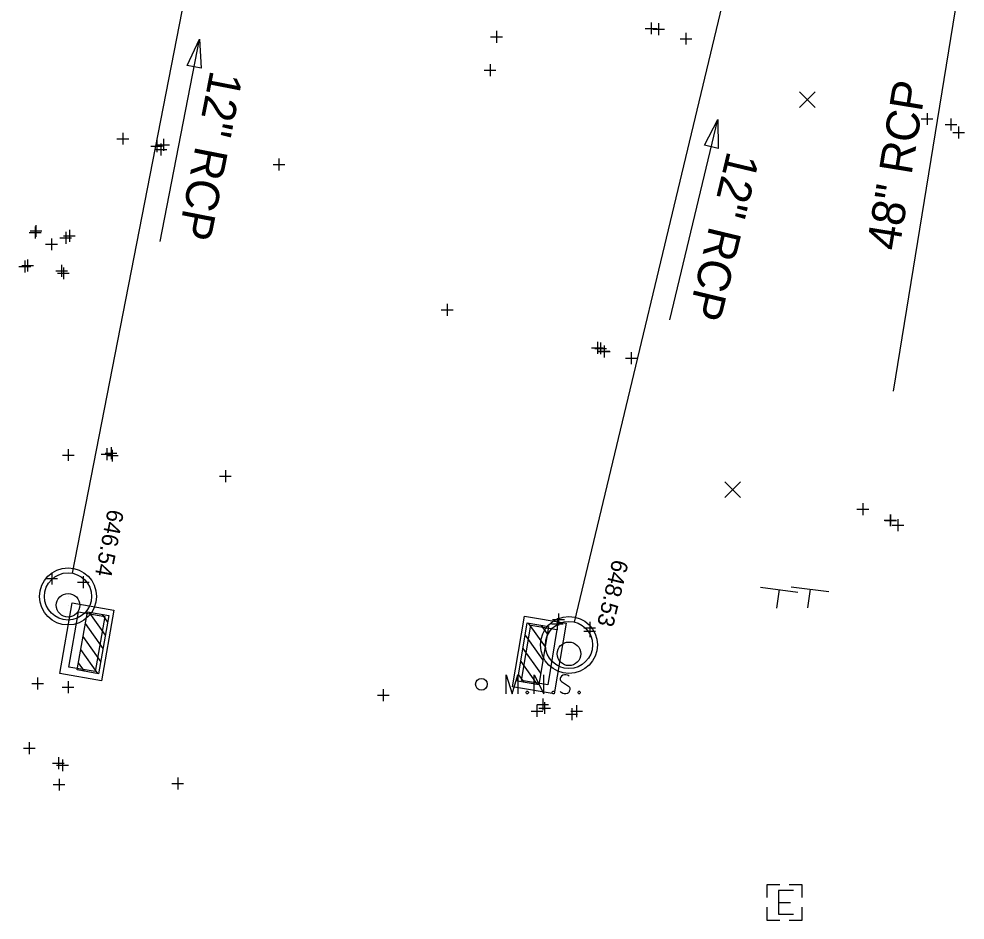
# Model space of a CAD drawing. Extents: x 2188719 to 2189819, y 654569 to 659504.
# Drawn here: x 2189542.6 to 2189622.9, y 656253.5 to 656329.9 of the extents above; entities that cross this region are included whole.
import ezdxf

# ---------------------------------------------------------------- set-up
doc = ezdxf.new("R2010")
doc.units = 0
for name, color, linetype in [('DR_X_Cells', 7, 'Continuous'), ('DR_X_Storm_Sewer', 7, 'Continuous'), ('DR_X_Text', 7, 'Continuous'), ('GK_Drainage_Nodes', 7, 'Continuous'), ('SC_Scratch1', 7, 'Continuous'), ('SN_X_Public', 7, 'Continuous'), ('SV_P_Control_Cells_Set', 7, 'Continuous'), ('SV_X_Random_Point', 7, 'Continuous'), ('SV_X_Shot_Marker', 7, 'Continuous'), ('UT_X_Electric_Cells', 7, 'Continuous')]:
    doc.layers.add(name, color=color, linetype=linetype)

msp = doc.modelspace()

# ---------------------------------------------------------------- linework, layer by layer
at = {"layer": 'DR_X_Cells'}
for p, q in [((2189549.977, 656277.639), (2189548.605, 656279.591)), ((2189550.173, 656278.752), (2189549.721, 656279.395)), ((2189549.781, 656276.526), (2189548.292, 656278.645)), ((2189585.812, 656278.663), (2189587.255, 656276.642)), ((2189586.929, 656278.475), (2189587.442, 656277.756)), ((2189585.563, 656277.635), (2189587.067, 656275.527)), ((2189549.585, 656275.414), (2189548.097, 656277.532)), ((2189549.329, 656274.387), (2189547.901, 656276.419)), ((2189585.375, 656276.521), (2189586.88, 656274.413)), ((2189548.213, 656274.583), (2189547.705, 656275.307)), ((2189585.188, 656275.406), (2189586.574, 656273.465)), ((2189585, 656274.292), (2189585.457, 656273.653))]:
    msp.add_line(p, q, dxfattribs=at)
for points in [[(2189546.107, 656274.404), (2189547.161, 656280.395), (2189550.691, 656279.774), (2189549.637, 656273.783)], [(2189546.88, 656274.945), (2189547.703, 656279.623), (2189549.919, 656279.233), (2189549.096, 656274.555)], [(2189547.597, 656274.692), (2189548.463, 656279.616), (2189550.269, 656279.298), (2189549.402, 656274.374)], [(2189589.034, 656278.67), (2189588.024, 656272.671), (2189584.49, 656273.266), (2189585.499, 656279.265)], [(2189587.546, 656278.371), (2189586.716, 656273.441), (2189584.908, 656273.745), (2189585.738, 656278.676)], [(2189588.265, 656278.124), (2189587.476, 656273.439), (2189585.258, 656273.813), (2189586.046, 656278.497)]]:
    msp.add_lwpolyline(points, close=True, dxfattribs=at)
for centre, radius in [((2189546.811, 656280.929), 2.417), ((2189546.811, 656280.929), 2), ((2189546.811, 656280.179), 1), ((2189589.279, 656276.813), 2.417), ((2189589.279, 656276.813), 2), ((2189589.279, 656276.063), 1)]:
    msp.add_circle(centre, radius, dxfattribs=at)
at = {"layer": 'DR_X_Storm_Sewer'}
for p, q in [((2189547.183, 656282.894), (2189561.205, 656354.68)), ((2189589.745, 656278.758), (2189605.751, 656345.53)), ((2189622.866, 656335.815), (2189616.759, 656298.323))]:
    msp.add_line(p, q, dxfattribs=at)
at = {"layer": 'DR_X_Text'}
for p, q in [((2189554.612, 656311.019), (2189557.965, 656328.181)), ((2189597.837, 656304.366), (2189601.913, 656321.37))]:
    msp.add_line(p, q, dxfattribs=at)
for points in [[(2189557.965, 656328.181), (2189558.093, 656325.711), (2189556.916, 656325.941)], [(2189601.913, 656321.37), (2189601.937, 656318.897), (2189600.771, 656319.176)]]:
    msp.add_lwpolyline(points, close=True, dxfattribs=at)
at = {"layer": 'GK_Drainage_Nodes'}
for p, q in [((2189546.811, 656282.929), (2189546.811, 656282.929)), ((2189546.811, 656280.929), (2189546.811, 656280.929)), ((2189546.811, 656280.929), (2189546.811, 656280.929)), ((2189546.811, 656280.179), (2189546.811, 656280.179)), ((2189548.811, 656279.428), (2189548.811, 656279.428)), ((2189546.811, 656278.929), (2189546.811, 656278.929)), ((2189589.279, 656278.813), (2189589.279, 656278.813)), ((2189587.155, 656278.31), (2189587.155, 656278.31)), ((2189546.635, 656277.4), (2189546.635, 656277.4)), ((2189547.291, 656277.284), (2189547.291, 656277.284)), ((2189548.03, 656277.154), (2189548.03, 656277.154)), ((2189548.03, 656277.154), (2189548.03, 656277.154)), ((2189548.399, 656277.089), (2189548.399, 656277.089)), ((2189549.507, 656276.894), (2189549.507, 656276.894)), ((2189550.164, 656276.778), (2189550.164, 656276.778)), ((2189589.279, 656276.813), (2189589.279, 656276.813)), ((2189589.279, 656276.813), (2189589.279, 656276.813)), ((2189584.994, 656276.266), (2189584.994, 656276.266)), ((2189585.652, 656276.155), (2189585.652, 656276.155)), ((2189586.761, 656275.968), (2189586.761, 656275.968)), ((2189589.279, 656276.063), (2189589.279, 656276.063)), ((2189587.131, 656275.906), (2189587.131, 656275.906)), ((2189587.131, 656275.906), (2189587.131, 656275.906)), ((2189587.871, 656275.782), (2189587.871, 656275.782)), ((2189588.528, 656275.671), (2189588.528, 656275.671)), ((2189547.988, 656274.75), (2189547.988, 656274.75)), ((2189589.279, 656274.813), (2189589.279, 656274.813)), ((2189586.367, 656273.626), (2189586.367, 656273.626))]:
    msp.add_line(p, q, dxfattribs=at)
for centre in [(2189546.811, 656280.929), (2189589.279, 656276.813)]:
    msp.add_circle(centre, 2, dxfattribs=at)
at = {"layer": 'SN_X_Public'}
for p, q in [((2189605.518, 656281.725), (2189608.688, 656281.293)), ((2189608.133, 656281.753), (2189611.307, 656281.345)), ((2189607.103, 656281.509), (2189606.887, 656279.924)), ((2189609.72, 656281.549), (2189609.516, 656279.962))]:
    msp.add_line(p, q, dxfattribs=at)
at = {"layer": 'SV_P_Control_Cells_Set'}
for points in [[(2189583.952, 656272.681), (2189583.952, 656274.281), (2189584.459, 656272.681), (2189584.944, 656274.281), (2189584.944, 656272.681)], [(2189586.322, 656272.681), (2189586.322, 656274.281), (2189587.149, 656272.681), (2189587.149, 656274.281)], [(2189589.299, 656274.168), (2189589.277, 656274.193), (2189589.243, 656274.218), (2189589.144, 656274.256), (2189589.023, 656274.281), (2189588.935, 656274.281), (2189588.902, 656274.281), (2189588.758, 656274.244), (2189588.637, 656274.168), (2189588.56, 656274.067), (2189588.538, 656273.966), (2189588.538, 656273.891), (2189588.56, 656273.79), (2189588.648, 656273.702), (2189589.255, 656273.324), (2189589.31, 656273.274), (2189589.332, 656273.223), (2189589.354, 656273.148), (2189589.354, 656273.072), (2189589.343, 656272.996), (2189589.332, 656272.946), (2189589.31, 656272.883), (2189589.288, 656272.833), (2189589.265, 656272.795), (2189589.232, 656272.757), (2189589.199, 656272.732), (2189589.155, 656272.707), (2189589.122, 656272.694), (2189589.023, 656272.681), (2189588.869, 656272.681), (2189588.77, 656272.707), (2189588.626, 656272.795), (2189588.538, 656272.87)], [(2189585.716, 656272.896), (2189585.771, 656272.896), (2189585.804, 656272.87), (2189585.837, 656272.82), (2189585.837, 656272.757), (2189585.804, 656272.707), (2189585.771, 656272.681), (2189585.716, 656272.681), (2189585.683, 656272.707), (2189585.65, 656272.757), (2189585.65, 656272.82), (2189585.683, 656272.87), (2189585.716, 656272.896)], [(2189587.932, 656272.896), (2189587.987, 656272.896), (2189588.02, 656272.87), (2189588.053, 656272.82), (2189588.053, 656272.757), (2189588.02, 656272.707), (2189587.987, 656272.681), (2189587.932, 656272.681), (2189587.899, 656272.707), (2189587.866, 656272.757), (2189587.866, 656272.82), (2189587.899, 656272.87), (2189587.932, 656272.896)], [(2189590.114, 656272.896), (2189590.169, 656272.896), (2189590.203, 656272.87), (2189590.235, 656272.82), (2189590.235, 656272.757), (2189590.203, 656272.707), (2189590.169, 656272.681), (2189590.114, 656272.681), (2189590.081, 656272.707), (2189590.048, 656272.757), (2189590.048, 656272.82), (2189590.081, 656272.87), (2189590.114, 656272.896)]]:
    msp.add_lwpolyline(points, dxfattribs=at)
msp.add_circle((2189581.862, 656273.481), 0.497, dxfattribs=at)
at = {"layer": 'SV_X_Random_Point'}
for p, q in [((2189608.818, 656322.368), (2189610.152, 656323.703)), ((2189608.818, 656323.703), (2189610.152, 656322.368)), ((2189602.504, 656289.313), (2189603.838, 656290.649)), ((2189602.504, 656290.649), (2189603.838, 656289.313))]:
    msp.add_line(p, q, dxfattribs=at)
at = {"layer": 'SV_X_Shot_Marker'}
for p, q in [((2189595.754, 656329.088), (2189596.754, 656329.088)), ((2189596.254, 656329.588), (2189596.254, 656328.588)), ((2189596.254, 656329.088), (2189596.254, 656329.088)), ((2189596.378, 656329.02), (2189597.378, 656329.02)), ((2189596.878, 656329.52), (2189596.878, 656328.52)), ((2189596.878, 656329.02), (2189596.878, 656329.02)), ((2189582.641, 656328.378), (2189583.641, 656328.378)), ((2189583.141, 656328.878), (2189583.141, 656327.878)), ((2189583.141, 656328.378), (2189583.141, 656328.378)), ((2189598.704, 656328.217), (2189599.704, 656328.217)), ((2189599.204, 656328.717), (2189599.204, 656327.717)), ((2189599.204, 656328.217), (2189599.204, 656328.217)), ((2189582.589, 656326.049), (2189582.589, 656325.049)), ((2189582.089, 656325.549), (2189583.089, 656325.549)), ((2189582.589, 656325.549), (2189582.589, 656325.549)), ((2189619.644, 656321.913), (2189619.644, 656320.913)), ((2189619.144, 656321.413), (2189620.144, 656321.413)), ((2189619.644, 656321.413), (2189619.644, 656321.413)), ((2189621.165, 656320.937), (2189622.165, 656320.937)), ((2189621.665, 656321.437), (2189621.665, 656320.437)), ((2189621.665, 656320.937), (2189621.665, 656320.937)), ((2189551.45, 656320.237), (2189551.45, 656319.237)), ((2189621.817, 656320.26), (2189622.817, 656320.26)), ((2189622.317, 656320.76), (2189622.317, 656319.76)), ((2189622.317, 656320.26), (2189622.317, 656320.26)), ((2189550.95, 656319.737), (2189551.95, 656319.737)), ((2189551.45, 656319.737), (2189551.45, 656319.737)), ((2189554.329, 656319.602), (2189554.329, 656318.602)), ((2189554.686, 656319.321), (2189554.686, 656318.321)), ((2189554.915, 656319.713), (2189554.915, 656318.713)), ((2189553.829, 656319.102), (2189554.829, 656319.102)), ((2189554.186, 656318.821), (2189555.186, 656318.821)), ((2189554.329, 656319.102), (2189554.329, 656319.102)), ((2189554.415, 656319.213), (2189555.415, 656319.213)), ((2189554.686, 656318.821), (2189554.686, 656318.821)), ((2189554.915, 656319.213), (2189554.915, 656319.213)), ((2189564.694, 656318.049), (2189564.694, 656317.049)), ((2189564.194, 656317.549), (2189565.194, 656317.549)), ((2189564.694, 656317.549), (2189564.694, 656317.549)), ((2189544.018, 656312.28), (2189544.018, 656311.28)), ((2189544.087, 656312.419), (2189544.087, 656311.419)), ((2189543.518, 656311.78), (2189544.518, 656311.78)), ((2189543.587, 656311.919), (2189544.587, 656311.919)), ((2189544.018, 656311.78), (2189544.018, 656311.78)), ((2189544.087, 656311.919), (2189544.087, 656311.919)), ((2189545.41, 656311.281), (2189545.41, 656310.281)), ((2189546.109, 656311.334), (2189547.109, 656311.334)), ((2189546.427, 656311.499), (2189547.427, 656311.499)), ((2189546.609, 656311.834), (2189546.609, 656310.834)), ((2189546.609, 656311.334), (2189546.609, 656311.334)), ((2189546.927, 656311.999), (2189546.927, 656310.999)), ((2189546.927, 656311.499), (2189546.927, 656311.499)), ((2189544.91, 656310.781), (2189545.91, 656310.781)), ((2189545.41, 656310.781), (2189545.41, 656310.781)), ((2189542.645, 656308.9), (2189543.645, 656308.9)), ((2189542.884, 656308.985), (2189543.884, 656308.985)), ((2189543.145, 656309.4), (2189543.145, 656308.4)), ((2189543.145, 656308.9), (2189543.145, 656308.9)), ((2189543.384, 656309.485), (2189543.384, 656308.485)), ((2189543.384, 656308.985), (2189543.384, 656308.985)), ((2189546.261, 656309.038), (2189546.261, 656308.038)), ((2189545.761, 656308.538), (2189546.761, 656308.538)), ((2189545.919, 656308.327), (2189546.919, 656308.327)), ((2189546.261, 656308.538), (2189546.261, 656308.538)), ((2189546.419, 656308.827), (2189546.419, 656307.827)), ((2189546.419, 656308.327), (2189546.419, 656308.327)), ((2189578.951, 656305.723), (2189578.951, 656304.723)), ((2189578.451, 656305.223), (2189579.451, 656305.223)), ((2189578.951, 656305.223), (2189578.951, 656305.223)), ((2189591.695, 656302.509), (2189591.695, 656301.509)), ((2189591.965, 656302.459), (2189591.965, 656301.459)), ((2189591.195, 656302.009), (2189592.195, 656302.009)), ((2189591.465, 656301.959), (2189592.465, 656301.959)), ((2189591.695, 656302.009), (2189591.695, 656302.009)), ((2189591.754, 656301.717), (2189592.754, 656301.717)), ((2189591.77, 656301.695), (2189592.77, 656301.695)), ((2189591.965, 656301.959), (2189591.965, 656301.959)), ((2189592.254, 656302.217), (2189592.254, 656301.217)), ((2189592.254, 656301.717), (2189592.254, 656301.717)), ((2189592.27, 656302.195), (2189592.27, 656301.195)), ((2189592.27, 656301.695), (2189592.27, 656301.695)), ((2189594.068, 656301.129), (2189595.068, 656301.129)), ((2189594.568, 656301.629), (2189594.568, 656300.629)), ((2189594.568, 656301.129), (2189594.568, 656301.129)), ((2189546.33, 656292.915), (2189547.33, 656292.915)), ((2189546.83, 656293.415), (2189546.83, 656292.415)), ((2189546.83, 656292.915), (2189546.83, 656292.915)), ((2189549.608, 656292.993), (2189550.608, 656292.993)), ((2189549.954, 656293.076), (2189550.954, 656293.076)), ((2189550.058, 656292.864), (2189551.058, 656292.864)), ((2189550.108, 656293.493), (2189550.108, 656292.493)), ((2189550.108, 656292.993), (2189550.108, 656292.993)), ((2189550.454, 656293.576), (2189550.454, 656292.576)), ((2189550.454, 656293.076), (2189550.454, 656293.076)), ((2189550.558, 656293.364), (2189550.558, 656292.364)), ((2189550.558, 656292.864), (2189550.558, 656292.864)), ((2189560.147, 656291.622), (2189560.147, 656290.622)), ((2189559.647, 656291.122), (2189560.647, 656291.122)), ((2189560.147, 656291.122), (2189560.147, 656291.122)), ((2189614.199, 656288.832), (2189614.199, 656287.832)), ((2189613.699, 656288.332), (2189614.699, 656288.332)), ((2189614.199, 656288.332), (2189614.199, 656288.332)), ((2189616.014, 656287.386), (2189617.014, 656287.386)), ((2189616.055, 656287.38), (2189617.055, 656287.38)), ((2189616.514, 656287.886), (2189616.514, 656286.886)), ((2189616.514, 656287.386), (2189616.514, 656287.386)), ((2189616.555, 656287.88), (2189616.555, 656286.88)), ((2189616.555, 656287.38), (2189616.555, 656287.38)), ((2189617.171, 656287.471), (2189617.171, 656286.471)), ((2189616.671, 656286.971), (2189617.671, 656286.971)), ((2189617.171, 656286.971), (2189617.171, 656286.971)), ((2189544.923, 656282.45), (2189545.923, 656282.45)), ((2189545.423, 656282.95), (2189545.423, 656281.95)), ((2189545.423, 656282.45), (2189545.423, 656282.45)), ((2189548.1, 656282.634), (2189548.1, 656281.634)), ((2189547.6, 656282.134), (2189548.6, 656282.134)), ((2189548.1, 656282.134), (2189548.1, 656282.134)), ((2189588.39, 656279.47), (2189588.39, 656278.47)), ((2189587.791, 656278.593), (2189588.791, 656278.593)), ((2189587.89, 656278.97), (2189588.89, 656278.97)), ((2189588.291, 656279.093), (2189588.291, 656278.093)), ((2189588.291, 656278.593), (2189588.291, 656278.593)), ((2189588.39, 656278.97), (2189588.39, 656278.97)), ((2189591.038, 656278.475), (2189591.038, 656277.475)), ((2189591.041, 656278.774), (2189591.041, 656277.774)), ((2189590.538, 656277.975), (2189591.538, 656277.975)), ((2189590.541, 656278.274), (2189591.541, 656278.274)), ((2189591.038, 656277.975), (2189591.038, 656277.975)), ((2189591.041, 656278.274), (2189591.041, 656278.274)), ((2189544.233, 656274.044), (2189544.233, 656273.044)), ((2189546.808, 656273.739), (2189546.808, 656272.739)), ((2189543.733, 656273.544), (2189544.733, 656273.544)), ((2189544.233, 656273.544), (2189544.233, 656273.544)), ((2189546.308, 656273.239), (2189547.308, 656273.239)), ((2189546.808, 656273.239), (2189546.808, 656273.239)), ((2189573.535, 656273.052), (2189573.535, 656272.052)), ((2189573.035, 656272.552), (2189574.035, 656272.552)), ((2189573.535, 656272.552), (2189573.535, 656272.552)), ((2189587.06, 656272.276), (2189587.06, 656271.276)), ((2189587.213, 656271.967), (2189587.213, 656270.967)), ((2189586.065, 656271.212), (2189587.065, 656271.212)), ((2189586.56, 656271.776), (2189587.56, 656271.776)), ((2189586.565, 656271.712), (2189586.565, 656270.712)), ((2189586.565, 656271.212), (2189586.565, 656271.212)), ((2189586.713, 656271.467), (2189587.713, 656271.467)), ((2189587.06, 656271.776), (2189587.06, 656271.776)), ((2189587.213, 656271.467), (2189587.213, 656271.467)), ((2189589.428, 656271.196), (2189590.428, 656271.196)), ((2189589.517, 656271.449), (2189589.517, 656270.449)), ((2189589.928, 656271.696), (2189589.928, 656270.696)), ((2189589.928, 656271.196), (2189589.928, 656271.196)), ((2189589.017, 656270.949), (2189590.017, 656270.949)), ((2189589.517, 656270.949), (2189589.517, 656270.949)), ((2189543.023, 656268.067), (2189544.023, 656268.067)), ((2189543.523, 656268.567), (2189543.523, 656267.567)), ((2189543.523, 656268.067), (2189543.523, 656268.067)), ((2189545.989, 656267.289), (2189545.989, 656266.289)), ((2189545.489, 656266.789), (2189546.489, 656266.789)), ((2189545.845, 656266.613), (2189546.845, 656266.613)), ((2189545.989, 656266.789), (2189545.989, 656266.789)), ((2189546.345, 656267.113), (2189546.345, 656266.113)), ((2189546.345, 656266.613), (2189546.345, 656266.613)), ((2189556.105, 656265.571), (2189556.105, 656264.571)), ((2189545.548, 656264.977), (2189546.548, 656264.977)), ((2189546.048, 656265.477), (2189546.048, 656264.477)), ((2189546.048, 656264.977), (2189546.048, 656264.977)), ((2189555.605, 656265.071), (2189556.605, 656265.071)), ((2189556.105, 656265.071), (2189556.105, 656265.071))]:
    msp.add_line(p, q, dxfattribs=at)
at = {"layer": 'UT_X_Electric_Cells'}
for p, q in [((2189607.06, 656254.989), (2189608.06, 656254.989)), ((2189607.56, 656254.989), (2189607.56, 656254.989))]:
    msp.add_line(p, q, dxfattribs=at)
for points in [[(2189607.16, 656256.489), (2189606.06, 656256.489), (2189606.06, 656255.389)], [(2189608.31, 656255.989), (2189607.06, 656255.989), (2189607.06, 656253.989), (2189608.31, 656253.989)], [(2189609.06, 656255.389), (2189609.06, 656256.489), (2189607.96, 656256.489)], [(2189606.06, 656254.589), (2189606.06, 656253.489), (2189607.16, 656253.489)], [(2189607.96, 656253.489), (2189609.06, 656253.489), (2189609.06, 656254.589)]]:
    msp.add_lwpolyline(points, dxfattribs=at)

# ---------------------------------------------------------------- texts
at = {"layer": 'DR_X_Text'}
for s, rotation, p in [('12" RCP', 258.94735, (2189558.89, 656325.616)), ('48" RCP', 80.74789, (2189617.268, 656310.157)), ('12" RCP', 256.52028, (2189602.729, 656318.768))]:
    msp.add_text(s, height=2.8, rotation=rotation, dxfattribs=at).set_placement(p)
at = {"layer": 'SC_Scratch1'}
for s, rotation, p in [('646.54', 258.94735, (2189550.189, 656288.376)), ('648.53', 256.52028, (2189592.987, 656284.132))]:
    msp.add_text(s, height=1.4, rotation=rotation, dxfattribs=at).set_placement(p)

doc.saveas('drawing.dxf')
